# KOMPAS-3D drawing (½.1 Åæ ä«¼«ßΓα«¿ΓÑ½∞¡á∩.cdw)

Views: Вид 1
Referenced files in C:\Program Files\ASCON\KOMPAS-3D V10\Sys\: Graphic.lcs
Referenced files in \\F-server\проектирование\Проекты\РЗА и ПА Тюменские РС\4. Проект\ЭП\Домостроительная\Рабочая документация\: План ПС Домостроительная.cdw
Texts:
  Ирина
  Текст на чертеже
  Размерные надписи
  Шероховатость
  Линия-выноска #1
  Линия-выноска #2
  Линия-выноска #3
  Отклонения формы и база
  Заголовок таблицы
  Ячейка таблицы
  Стрелка вида
  Обозначение изменения
  Фигурная скобка
  Номер узла
  Марка координационной оси
  VRCB
  Выносная надпись
  Обозначение узла
  Марка/позиционное обозначение с линией-выноской
  Марка/позиционное обозначение на линии
  Марка/позиционное обозначение без линии-выноски
  Normal
  Лит-Масса-Масштаб
  Материал-Предприятие
  Title Specification
  Body Specification ( left align )
  Body Specificaton ( centered )
  Без имени
  heading 1
  Знак Знак Знак Знак Знак Знак
  Verdana
  Body Text
  MS Sans Serif
  Txt
  Simplex
  TXT
  Обычный
  Термин
  Список определений
  Адрес
  Цитаты
  Форматированный
  Courier New
  Z-конец формы
  Z-начало формы
  Additional DXF text style 0
  Абзац Знак
  Body Text 3
  Title
  ТекстШаг1
  Шрифт 2.5
  Заголовки
  txt
  heading 2
  AGOpus
  footer
  Денис
  RUSTXT
  Обычный (веб)
  ООббыыччнныыйй
  Definition Term
  Definition List
  Address
  Blockquote
  Preformatted
  z-Bottom of Form
  z-Top of Form
  header
  NormalParagraphStyle
  ссылки
  Подпись в квадратике
  табл
  цепи
  Маркировка
  клеммы, контакты
  тексты табл
  Тексты. 3,2
  ЗОНА_привяз
  текст переноса
  ТТееррммиинн
  ССппииссоокк ооппррееддееллеенниийй
  ААддрреесс
  ЦЦииттааттыы
  ФФооррммааттиирроовваанннныыйй
  Z-ккооннеецц ффооррммыы
  Z-ннааччааллоо ффооррммыы
  GOST 2.304 type A
  rustxt
  heading 8
  heading 3
  heading 6
  heading 7
  russ
  heading 4
  heading 5
  heading 9
  HeliosLight
  Pa3
  Pa1
  Три с половиной
  style2
  Table Contents
  Table Heading
  ГОСТ_МНЕ
  ESK - Обозначение
  маркировка
  ISOCP
  ROMANS
  SIMPLEX
  Текст 3,5
  Tahoma
  CNBNDG+TimesNewRoman
  Subtitle
  FR5
  ISOCPEUR
  romanc
  Аппараты
  Ссылки
  подписи
  Состав чартежа
  Клеммник текст
  ячейка табл.
  Пояснения
  CC С?т?и?л?ь? П?о? ц?е?н?т?р?у?
  Normal (Web)
  Ошиновка
  Топо
  ВЛ 110 кВ
  Тюмень-500
  Тюменская ТЭЦ
  - предупреждающий знак
  "Опасно. Возможно падение груза"
  "Опасность поражения электрическим током"
  - стоянка крана во время производства работ
  Экспликация зданий и сооружений
  Номер
  на плане
  Постоянные здания и сооружения
  ОПУ-IV
  Существующее
  ЗРУ-10 кВ
  Трансформатор 1Т, маслоприемник
  Существующий
  Трансформатор 2Т, маслоприемник
  Временные здания и сооружения
  III
  Вагон-дом для кратковременного отдыха рабочих
  Уборная
  Дизельная электростанция
  Контейнеры для ТБО (0,75м 3 ) и жидких хоз.-быт.стоков(1м 3 )
  «Екатерина» 9,0х3,0
  Туалетная кабина "Люкс"
  ОАО ПКТИпромстрой
  - стенд с противопожарным инвентарем
  - знак ограничения поворота стрелы
  - опасная зона работы
  при перемещении грузов
  Примечания:
  1. Для нужд строительства (размещение задействованного в строительстве персонала, обеспечение электроэнергией) использовать
  временные мобильные инвентарные здания;
  2. При выполнении всех строительно-монтажных работ на площадке необходимо руководствоваться требованиями СНиП 12-03-2001
  "Безопасность труда в строительстве. Общие требования",  СНиП 12-04-2002 "Безопасность труда в строительстве. Строительное
  производство", а также ПОТ-РМ-016-2001/РД 153-34.0-03.150-00 "Межотраслевые правила по охране труда  (правила безопасности)
  при эксплуатации электроустановок";
  3. На паспорте-стенде строительного объекта  должен быть план пожарной защиты с нанесенными строящимися и вспомогательными
  зданиями и сооружениями, въездами, подъездами, местонахождениями водоисточников, средств пожаротушения и связи (согласно
  ППБ-01-03 п.575);
  4. Наружное освещение строительной площадки осуществляется за счет существующего освещения;
  5. Под временные сооружения (поз. II, III и IV) устраивается площадка из дорожных плит ПД 60-20 на щебеночном основании толщиной 15см;
  6. На период строительства для электроснабжения временных зданий и сооружений использовать дизельную  электростанцию.
  Прокладку кабеля от дизельной электростанции до вагончиков выполнить в воздушном исполнении в гофрированной трубе диаметром
  30 мм, на вагончиках кабель закрепить скобами. Щиток временного электроснабжения навесить на стенку вагона-дома для отдыха рабочих;
  7. Тонкой линией изображено существующее оборудование, замена которого проектом не предусматривается,  утолщенной - вновь
  устанавливаемое оборудование.
  8. Грузовысотные характеристики КМУ ИНМАН ИМ-150 см. 16/01-ПОС,л.7.
  - пути перемещения
  строительной техники
  Условные обозначения:
  - паспорт-стенд строительного
  объекта
  - запрещающий знак ограничения
  скорости движения автомобиля
  КМУ ИНМАН ИМ-150
  АГП-22
  POLYLINE_STYLE_0.18_RGB_0_0_0
  POLYLINE_STYLE_0.20_RGB_0_0_0
  POLYLINE_STYLE_0.18_RGB_0_80_80
  Бортовой автомобиль КамАЗ 43114-027-02
  АТ ППР#010#0104
  АГП
  Автогидроподъемник АГП-18-04
  АГП ППР#140#0102
  Шашерин
  Королева
  Разраб.
  Перезавод ВЛ на ПС Тюмень. Реконструкция устройств
  РЗ и ПА на обратных концах отходящих ВЛ,
  ВОЛС Тюменского ТПО
  Строительный генеральный план
  Ведомость эскизного проекта
  ПС 110/10 кВ Домостроительная
  ГИП
  Матвеев
  Ромин
Dimensions and other numbers on the sheet: 16/01-ПОС; 7; 2,5; 1,8; 2.5; 3,2_; 3.5; 3,2; 2,5 (контакты, клеммы); 3,2 (надписи); 3,2 (Зоны); 5; 2,5_01; 2,5_3; 3,5_01; 3,5_tabl; 5_заголовок; 2,3_; 3,2_зона не привяз; 3,5; 3.2 маркировка; 3,2 элементы; 3,2 линия; 3,2 таблица; 2,5 грязносинь; 2.5 курсив; 2.5_Э5_надписи; 2.5_Э5_ссылки; 2.5_кабель; 3.2; 2.5 надписи; 3 и 5; 5,0_белый_подчёркнутый; 3.2 фиол; 3.2 (текст); 4; 1; 2; 3; 9,6; 05.13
